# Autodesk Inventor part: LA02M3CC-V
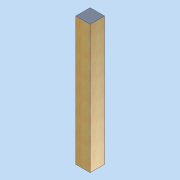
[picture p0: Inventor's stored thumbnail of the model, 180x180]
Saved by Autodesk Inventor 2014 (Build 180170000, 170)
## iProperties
Created: 2013-02
Part Number: LA02M3CC-V
Document SubType Name: Modeling
Designer: david.appleford
Density: 0.398379 g/cm^3
Description: Lug Middle 0.5w 3 Slots
Cost Center: £6.00
Mass: 1120 g
Surface Area: 1746.24 cm^2
Volume: 2811.39 cm^3
Material: 000 Redwood
Appearance: Wood (Pine)
Justset: False
Author: david.appleford
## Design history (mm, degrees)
sketch "Sketch1"
  geometry: L1 (0, 0)-(68, 0); L2 (68, 0)-(68, 68); L3 (68, 68)-(0, 68); L4 (0, 68)-(0, 0)
  constraints: 8 end point, 2 parallel, 1 horizontal, 1 perpendicular
  dimensions: "d0" = 68 distance between parallel lines of L2 L4 (= t); "d1" = 68 distance between parallel lines of L1 L3 (= t)
extrude "Extrusion1" new body sketch "Sketch1" distance "d2" = 608 (= 0.5 x w - Cl); taper "d3" = 0 deg
body "Solid1"
other parameters: "t" = 68 [user parameter; used in 2 equation terms], "Cl" = 2 [user parameter; used in 1 equation term]
